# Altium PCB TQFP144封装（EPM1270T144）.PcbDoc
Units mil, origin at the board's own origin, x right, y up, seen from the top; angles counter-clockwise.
Board outline 6000 x 4000 mil, 2 copper layers (Top Layer, Bottom Layer); 1 components, 0 nets, 144 pads, 0 vias.
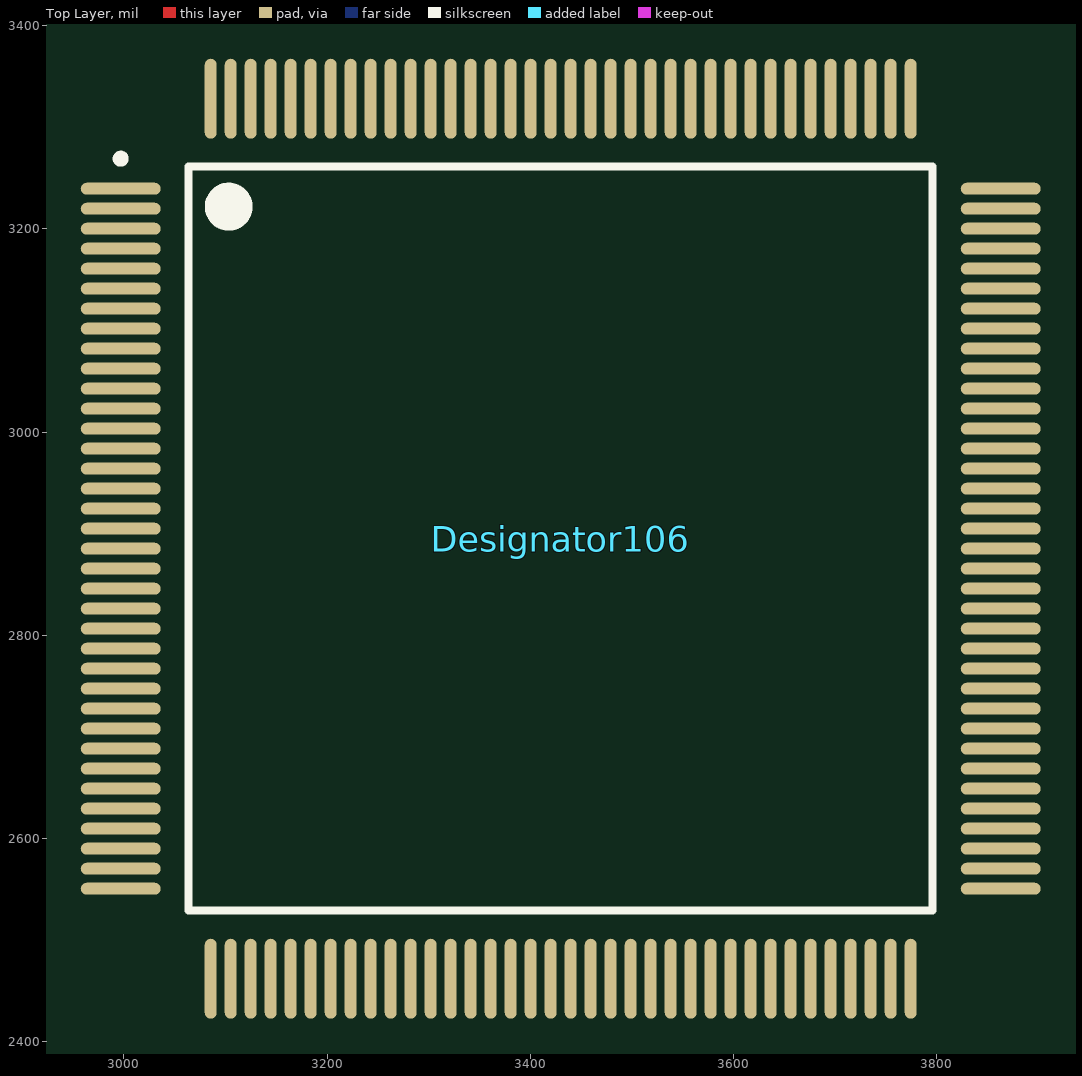
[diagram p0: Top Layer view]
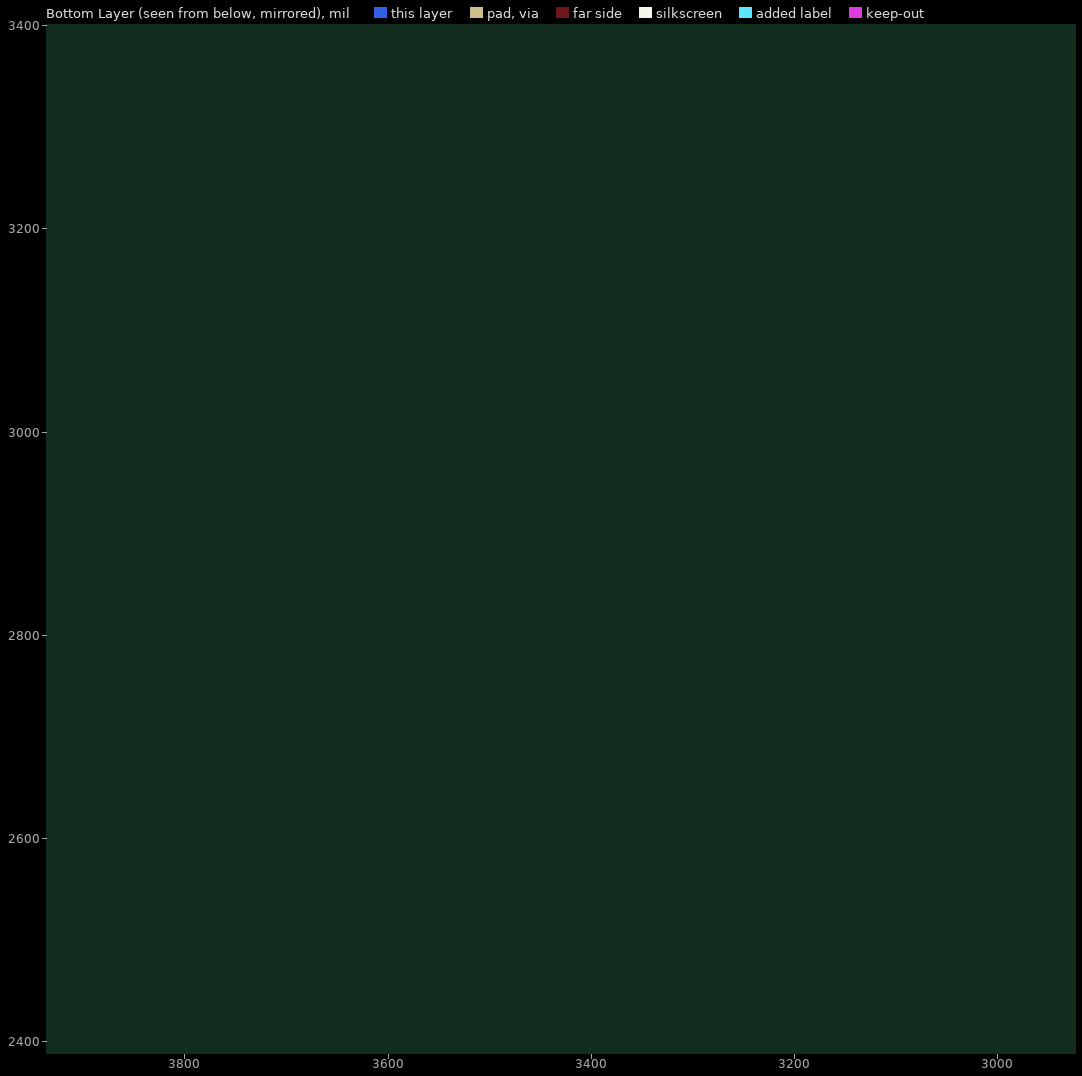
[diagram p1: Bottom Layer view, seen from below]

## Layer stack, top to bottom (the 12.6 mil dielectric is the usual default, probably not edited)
Top Solder: solder mask 0.4, Solder Resist, Dk 3.5
Top Layer: signal copper 1.4
Dielectric 1: dielectric 12.6, FR-4, Dk 4.8
Bottom Layer: signal copper 1.4
Bottom Solder: solder mask 0.4, Solder Resist, Dk 3.5

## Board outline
1000,1000 7000,1000 7000,5000 1000,5000

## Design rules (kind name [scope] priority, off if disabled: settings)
Clearance [All] p1: gap=10
PolygonConnect [All] p1: connectstyle=Relief reliefconductorwidth=10 reliefentries=4 polygonreliefangle="90 Angle" airgapwidth=10
RoutingVias [All] p1: holewidth=28 width=50 viastyle="Through Hole" minholewidth=28 minwidth=50 maxholewidth=28 maxwidth=50
SolderMaskExpansion [All] p1: expansion=4
Width [All] p1: maxlimit=10 minlimit=10 preferedwidth=10
30 further rules are at their usual default settings.

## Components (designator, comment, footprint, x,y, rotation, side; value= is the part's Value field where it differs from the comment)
Designator106 "Comment" TQFP144 3430,2895 r0 top

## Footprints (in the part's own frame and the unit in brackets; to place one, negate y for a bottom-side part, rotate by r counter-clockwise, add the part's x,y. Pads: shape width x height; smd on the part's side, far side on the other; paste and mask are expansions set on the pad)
TQFP144 [mm]
  oval 2x0.3 smd: 1(-11,8.75) 2(-11,8.25) 3(-11,7.75) 4(-11,7.25) 5(-11,6.75) 6(-11,6.25) 7(-11,5.75) 8(-11,5.25) 9(-11,4.75) 10(-11,4.25) 11(-11,3.75) 12(-11,3.25) 13(-11,2.75) 14(-11,2.25) 15(-11,1.75) 16(-11,1.25) 17(-11,0.75) 18(-11,0.25) 19(-11,-0.25) 20(-11,-0.75) 21(-11,-1.25) 22(-11,-1.75) 23(-11,-2.25) 24(-11,-2.75) 25(-11,-3.25) 26(-11,-3.75) 27(-11,-4.25) 28(-11,-4.75) 29(-11,-5.25) 30(-11,-5.75) 31(-11,-6.25) 32(-11,-6.75) 33(-11,-7.25) 34(-11,-7.75) 35(-11,-8.25) 36(-11,-8.75) 73(11,-8.75) 74(11,-8.25) 75(11,-7.75) 76(11,-7.25) 77(11,-6.75) 78(11,-6.25) 79(11,-5.75) 80(11,-5.25) 81(11,-4.75) 82(11,-4.25) 83(11,-3.75) 84(11,-3.25) 85(11,-2.75) 86(11,-2.25) 87(11,-1.75) 88(11,-1.25) 89(11,-0.75) 90(11,-0.25) 91(11,0.25) 92(11,0.75) 93(11,1.25) 94(11,1.75) 95(11,2.25) 96(11,2.75) 97(11,3.25) 98(11,3.75) 99(11,4.25) 100(11,4.75) 101(11,5.25) 102(11,5.75) 103(11,6.25) 104(11,6.75) 105(11,7.25) 106(11,7.75) 107(11,8.25) 108(11,8.75)
  oval 0.3x2 smd: 37(-8.75,-11) 38(-8.25,-11) 39(-7.75,-11) 40(-7.25,-11) 41(-6.75,-11) 42(-6.25,-11) 43(-5.75,-11) 44(-5.25,-11) 45(-4.75,-11) 46(-4.25,-11) 47(-3.75,-11) 48(-3.25,-11) 49(-2.75,-11) 50(-2.25,-11) 51(-1.75,-11) 52(-1.25,-11) 53(-0.75,-11) 54(-0.25,-11) 55(0.25,-11) 56(0.75,-11) 57(1.25,-11) 58(1.75,-11) 59(2.25,-11) 60(2.75,-11) 61(3.25,-11) 62(3.75,-11) 63(4.25,-11) 64(4.75,-11) 65(5.25,-11) 66(5.75,-11) 67(6.25,-11) 68(6.75,-11) 69(7.25,-11) 70(7.75,-11) 71(8.25,-11) 72(8.75,-11) 109(8.75,11) 110(8.25,11) 111(7.75,11) 112(7.25,11) 113(6.75,11) 114(6.25,11) 115(5.75,11) 116(5.25,11) 117(4.75,11) 118(4.25,11) 119(3.75,11) 120(3.25,11) 121(2.75,11) 122(2.25,11) 123(1.75,11) 124(1.25,11) 125(0.75,11) 126(0.25,11) 127(-0.25,11) 128(-0.75,11) 129(-1.25,11) 130(-1.75,11) 131(-2.25,11) 132(-2.75,11) 133(-3.25,11) 134(-3.75,11) 135(-4.25,11) 136(-4.75,11) 137(-5.25,11) 138(-5.75,11) 139(-6.25,11) 140(-6.75,11) 141(-7.25,11) 142(-7.75,11) 143(-8.25,11) 144(-8.75,11)
  silkscreen extent -11.1,-9.3 9.3,9.6

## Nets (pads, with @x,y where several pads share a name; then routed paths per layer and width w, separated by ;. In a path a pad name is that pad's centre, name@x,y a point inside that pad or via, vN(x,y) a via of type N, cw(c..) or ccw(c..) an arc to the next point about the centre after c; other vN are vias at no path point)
pads on no net: Designator106.1 Designator106.2 Designator106.3 Designator106.4 Designator106.5 Designator106.6 Designator106.7 Designator106.8 Designator106.9 Designator106.10 Designator106.11 Designator106.12 Designator106.13 Designator106.14 Designator106.15 Designator106.16 Designator106.17 Designator106.18 Designator106.19 Designator106.20 Designator106.21 Designator106.22 Designator106.23 Designator106.24 Designator106.25 Designator106.26 Designator106.27 Designator106.28 Designator106.29 Designator106.30 Designator106.31 Designator106.32 Designator106.33 Designator106.34 Designator106.35 Designator106.36 Designator106.37 Designator106.38 Designator106.39 Designator106.40 Designator106.41 Designator106.42 Designator106.43 Designator106.44 Designator106.45 Designator106.46 Designator106.47 Designator106.48 Designator106.49 Designator106.50 Designator106.51 Designator106.52 Designator106.53 Designator106.54 Designator106.55 Designator106.56 Designator106.57 Designator106.58 Designator106.59 Designator106.60 Designator106.61 Designator106.62 Designator106.63 Designator106.64 Designator106.65 Designator106.66 Designator106.67 Designator106.68 Designator106.69 Designator106.70 Designator106.71 Designator106.72 Designator106.73 Designator106.74 Designator106.75 Designator106.76 Designator106.77 Designator106.78 Designator106.79 Designator106.80 Designator106.81 Designator106.82 Designator106.83 Designator106.84 Designator106.85 Designator106.86 Designator106.87 Designator106.88 Designator106.89 Designator106.90 Designator106.91 Designator106.92 Designator106.93 Designator106.94 Designator106.95 Designator106.96 Designator106.97 Designator106.98 Designator106.99 Designator106.100 Designator106.101 Designator106.102 Designator106.103 Designator106.104 Designator106.105 Designator106.106 Designator106.107 Designator106.108 Designator106.109 Designator106.110 Designator106.111 Designator106.112 Designator106.113 Designator106.114 Designator106.115 Designator106.116 Designator106.117 Designator106.118 Designator106.119 Designator106.120 Designator106.121 Designator106.122 Designator106.123 Designator106.124 Designator106.125 Designator106.126 Designator106.127 Designator106.128 Designator106.129 Designator106.130 Designator106.131 Designator106.132 Designator106.133 Designator106.134 Designator106.135 Designator106.136 Designator106.137 Designator106.138 Designator106.139 Designator106.140 Designator106.141 Designator106.142 Designator106.143 Designator106.144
